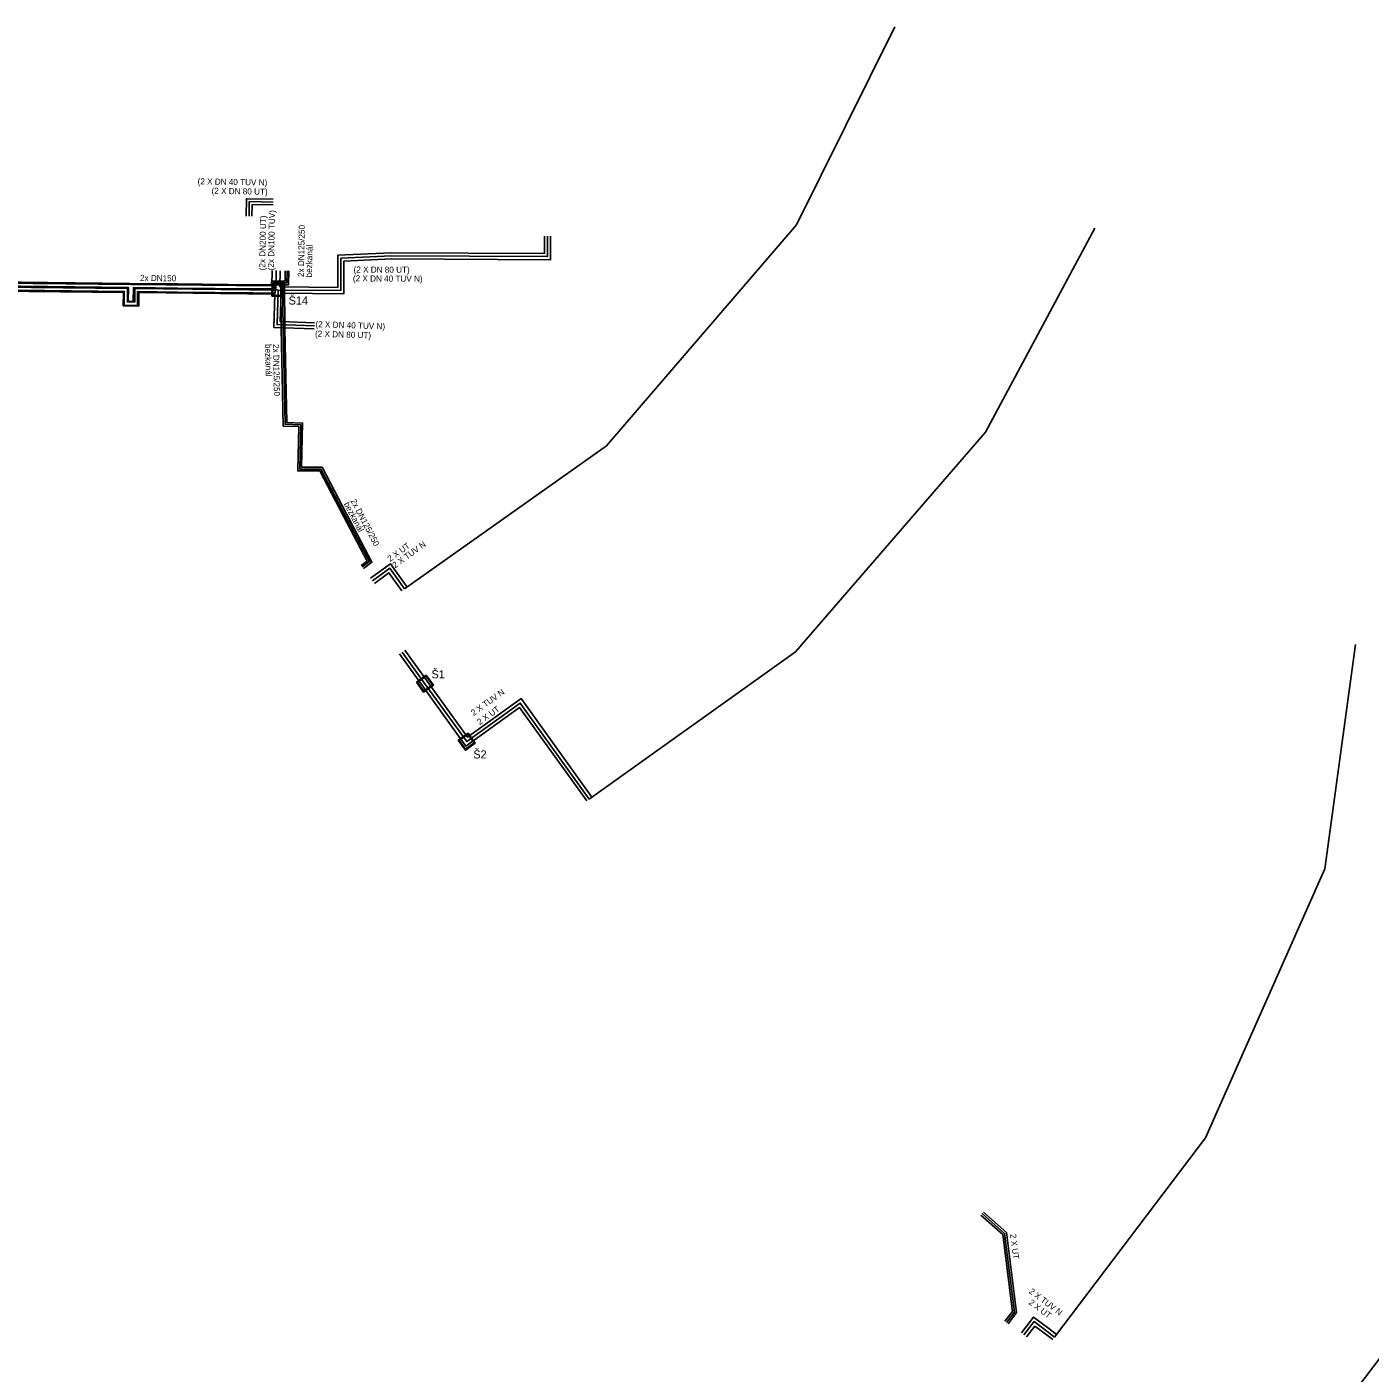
# Model space of a CAD drawing. Extents: x -606118 to -604472, y -1157869 to -1156854.
# Drawn here: x -605139.3 to -604808.5, y -1157466.1 to -1157134.5 of the extents above; entities that cross this region are included whole.
import ezdxf

# ---------------------------------------------------------------- set-up
doc = ezdxf.new("R2010")
doc.units = 0
for name, color, linetype in [('Osa trasy teplovodu', 7, 'Continuous'), ('označení šachty', 7, 'Continuous'), ('Teplovod - trasa - okraj', 7, 'Continuous'), ('Teplovod - trasa popis', 7, 'Continuous'), ('Teplovod - trasa popis 2', 7, 'Continuous'), ('Šachta trasy teplovodu', 7, 'Continuous')]:
    doc.layers.add(name, color=color, linetype=linetype)

msp = doc.modelspace()

# ---------------------------------------------------------------- linework, layer by layer
at = {"layer": 'Osa trasy teplovodu'}
for p, q in [((-605077.9, -1157194.56), (-605078, -1157199.33)), ((-604829.05, -1157492.68), (-604799.91, -1157454.18)), ((-604888.12, -1157455.75), (-604886.18, -1157457.22))]:
    msp.add_line(p, q, dxfattribs=at)
for points in [[(-605046.31, -1157272.96), (-604996.53, -1157237.75), (-604949.8, -1157183.3), (-604925.57, -1157134.54)], [(-605084.59, -1157181.14), (-605084.54, -1157177.57), (-605078.66, -1157177.68)], [(-605077.45, -1157199.34), (-605062, -1157199.5), (-605061.98, -1157191.49), (-605049.54, -1157190.9), (-605011.1, -1157191.11), (-605011.09, -1157186.11)], [(-605000.79, -1157324.72), (-604950.04, -1157288.49), (-604903.17, -1157234.33), (-604876.29, -1157184.14)], [(-605076.34, -1157197.59), (-605075.3, -1157197.59), (-605075.24, -1157194.62)], [(-605169.85, -1157198.38), (-605114.56, -1157198.95), (-605114.57, -1157202.26), (-605112.73, -1157202.28), (-605112.71, -1157198.97), (-605077.45, -1157199.34)], [(-605169.6, -1157198.05), (-605167.51, -1157198.07), (-605114.32, -1157198.71), (-605114.34, -1157202.16), (-605113.1, -1157202.17), (-605113.05, -1157198.72), (-605102.26, -1157198.85), (-605083.64, -1157199.07), (-605082.78, -1157199.08), (-605078.61, -1157199.08)], [(-605078.61, -1157199.08), (-605078.61, -1157197.59), (-605076.34, -1157197.59)], [(-605077.45, -1157199.34), (-605077.7, -1157207.84), (-605068.51, -1157208.14)], [(-605076.34, -1157197.59), (-605076.2, -1157208.81), (-605075.96, -1157220.61), (-605075.73, -1157232.41), (-605071.86, -1157232.54), (-605072.13, -1157243.45), (-605066.88, -1157243.43), (-605060.9, -1157254.84), (-605054.92, -1157266.24), (-605056.7, -1157267.54)], [(-605054.2, -1157270.97), (-605049.96, -1157267.88), (-605046.31, -1157272.96)], [(-605046.91, -1157288.51), (-605041.28, -1157296.3), (-605030.98, -1157310.58), (-605017.79, -1157301.06), (-605000.79, -1157324.72)], [(-604886.18, -1157457.22), (-604849.05, -1157408.16), (-604819.65, -1157341.94), (-604812.06, -1157286.61)], [(-604898.01, -1157453.62), (-604896.07, -1157451.08), (-604898.51, -1157431.7), (-604904, -1157426.83)], [(-604893.74, -1157456.7), (-604891.2, -1157453.43), (-604888.12, -1157455.75)]]:
    msp.add_lwpolyline(points, dxfattribs=at)
at = {"layer": 'Teplovod - trasa - okraj'}
for p, q in [((-605078.9, -1157194.54), (-605078.98, -1157198.32)), ((-605076.9, -1157194.58), (-605076.98, -1157198.59)), ((-604886.66, -1157457.85), (-604888.61, -1157456.39)), ((-604887.64, -1157455.11), (-604885.7, -1157456.58))]:
    msp.add_line(p, q, dxfattribs=at)
for points in [[(-605046.31, -1157272.96), (-604996.53, -1157237.75), (-604949.8, -1157183.3), (-604925.57, -1157134.54)], [(-605085.29, -1157181.12), (-605085.23, -1157176.86), (-605078.65, -1157176.98)], [(-605083.89, -1157181.15), (-605083.85, -1157178.29), (-605078.67, -1157178.38)], [(-605076.98, -1157198.59), (-605062.75, -1157198.74), (-605062.73, -1157190.78), (-605049.55, -1157190.15), (-605011.85, -1157190.36), (-605011.84, -1157186.11)], [(-605076.72, -1157200.09), (-605061.25, -1157200.26), (-605061.23, -1157192.21), (-605049.52, -1157191.65), (-605010.35, -1157191.87), (-605010.34, -1157186.11)], [(-605000.79, -1157324.72), (-604950.04, -1157288.49), (-604903.17, -1157234.33), (-604876.29, -1157184.14)], [(-605076.34, -1157197.15), (-605075.74, -1157197.15), (-605075.69, -1157194.61)], [(-605074.79, -1157194.63), (-605074.85, -1157198.04), (-605075.89, -1157198.04)], [(-605170.04, -1157197.05), (-605167.5, -1157197.07), (-605114.03, -1157197.71), (-605114.03, -1157197.7), (-605102.25, -1157197.85), (-605083.63, -1157198.07), (-605082.78, -1157198.08), (-605079.06, -1157198.08)], [(-605078.23, -1157200.33), (-605111.72, -1157199.98), (-605111.74, -1157203.28), (-605115.57, -1157203.25), (-605115.56, -1157199.94), (-605169.86, -1157199.38)], [(-605169.84, -1157197.38), (-605113.71, -1157197.96), (-605113.71, -1157197.96), (-605078.98, -1157198.32)], [(-605078.17, -1157200.08), (-605082.79, -1157200.08), (-605083.65, -1157200.07), (-605102.27, -1157199.85), (-605112.06, -1157199.73), (-605112.11, -1157203.19), (-605115.35, -1157203.14), (-605115.32, -1157199.69), (-605167.52, -1157199.07), (-605169.15, -1157199.06)], [(-605079.06, -1157198.08), (-605079.06, -1157197.14), (-605076.34, -1157197.15)], [(-605076.79, -1157198.04), (-605078.16, -1157198.04), (-605078.17, -1157200.08)], [(-605056.96, -1157267.17), (-605055.5, -1157266.11), (-605061.3, -1157255.05), (-605067.15, -1157243.88), (-605072.59, -1157243.9), (-605072.32, -1157232.98), (-605076.17, -1157232.84), (-605076.41, -1157220.62), (-605076.65, -1157208.82), (-605076.79, -1157198.04)], [(-605075.89, -1157198.04), (-605075.75, -1157208.8), (-605075.51, -1157220.6), (-605075.28, -1157231.98), (-605071.4, -1157232.11), (-605071.67, -1157243), (-605066.61, -1157242.98), (-605060.5, -1157254.63), (-605054.34, -1157266.38), (-605056.43, -1157267.9)], [(-605078.23, -1157200.33), (-605078.47, -1157208.56), (-605068.54, -1157208.89)], [(-605076.72, -1157200.09), (-605076.93, -1157207.11), (-605068.49, -1157207.39)], [(-605054.68, -1157270.32), (-605049.78, -1157266.76), (-605045.66, -1157272.5)], [(-605053.73, -1157271.62), (-605050.14, -1157269), (-605046.96, -1157273.43)], [(-605047.56, -1157288.98), (-605031.17, -1157311.7), (-605017.97, -1157302.18), (-605001.44, -1157325.19)], [(-605046.26, -1157288.04), (-605030.8, -1157309.46), (-605017.61, -1157299.94), (-605000.14, -1157324.26)], [(-604886.18, -1157457.22), (-604849.05, -1157408.16), (-604819.65, -1157341.94), (-604812.06, -1157286.61)], [(-604898.41, -1157453.32), (-604896.59, -1157450.94), (-604898.98, -1157431.95), (-604904.33, -1157427.21)], [(-604897.61, -1157453.93), (-604895.55, -1157451.22), (-604898.04, -1157431.45), (-604903.67, -1157426.46)], [(-604894.37, -1157456.21), (-604891.35, -1157452.31), (-604891.35, -1157452.31), (-604887.64, -1157455.11)], [(-604888.61, -1157456.39), (-604891.05, -1157454.54), (-604893.11, -1157457.19)]]:
    msp.add_lwpolyline(points, dxfattribs=at)
at = {"layer": 'Šachta trasy teplovodu'}
for points in [[(-605078.97, -1157200.82), (-605078.94, -1157197.82), (-605075.93, -1157197.85), (-605075.96, -1157200.85), (-605078.97, -1157200.82)], [(-605076.15, -1157200.66), (-605076.12, -1157198.03), (-605078.75, -1157198.01), (-605078.78, -1157200.64), (-605076.15, -1157200.66)], [(-605043.38, -1157295.96), (-605040.94, -1157294.21), (-605039.18, -1157296.64), (-605041.62, -1157298.4), (-605043.38, -1157295.96)], [(-605041.58, -1157298.14), (-605039.44, -1157296.6), (-605040.98, -1157294.47), (-605043.12, -1157296.01), (-605041.58, -1157298.14)], [(-605033.08, -1157310.24), (-605030.64, -1157308.48), (-605028.88, -1157310.92), (-605031.32, -1157312.68), (-605033.08, -1157310.24)], [(-605031.28, -1157312.41), (-605029.15, -1157310.88), (-605030.68, -1157308.74), (-605032.82, -1157310.28), (-605031.28, -1157312.41)]]:
    msp.add_lwpolyline(points, dxfattribs=at)

# ---------------------------------------------------------------- texts
at = {"layer": 'označení šachty'}
for s, p in [('Š14', (-605074.85, -1157202.93)), ('Š1', (-605039.66, -1157294.98)), ('Š2', (-605029.36, -1157314.72))]:
    msp.add_text(s, height=2, dxfattribs=at).set_placement(p)
at = {"layer": 'Teplovod - trasa popis'}
for s, rotation, p in [('(2 X DN 80 UT)', 359.0153, (-605093.84, -1157175.65)), ('(2x DN200 UT)', 88.8701, (-605080.64, -1157194.5)), ('2x DN125/250', 88.8646, (-605071.1, -1157196.15)), ('2x DN150', 359.3064, (-605111.47, -1157197.11)), ('(2 X DN 80 UT)', 359.7029, (-605058.85, -1157195.04)), ('(2 X DN 80 UT)', 358.1559, (-605068.37, -1157210.82)), ('2x DN125/250', 271.141, (-605078.71, -1157212.65)), ('2x DN125/250', 297.6804, (-605059.66, -1157251.26)), ('2 X UT', 36.039, (-605049.84, -1157266.34)), ('2 X UT', 35.8099, (-605027.77, -1157306.55)), ('2 X UT ', 277.197, (-604897.16, -1157431.92)), ('2 X UT ', 322.9763, (-604892.7, -1157448.99))]:
    msp.add_text(s, height=1.5, rotation=rotation, dxfattribs=at).set_placement(p)
at = {"layer": 'Teplovod - trasa popis 2'}
for s, rotation, p in [('(2 X DN 40 TUV N)', 359.0153, (-605097.28, -1157173.31)), ('(2x DN100 TUV)', 88.8701, (-605078.48, -1157194.5)), ('bezkanál', 88.8646, (-605069.11, -1157196.24)), ('(2 X DN 40 TUV N)', 359.7029, (-605059.02, -1157197.22)), ('(2 X DN 40 TUV N)', 358.1559, (-605068.26, -1157208.49)), ('bezkanál', 271.141, (-605080.64, -1157212.65)), ('bezkanál', 297.6804, (-605061.3, -1157252.03)), ('2 X TUV N', 36.039, (-605048.63, -1157267.94)), ('2 X TUV N', 35.8099, (-605029.29, -1157304.3)), ('2 X TUV N', 322.9763, (-604892.64, -1157446.25))]:
    msp.add_text(s, height=1.5, rotation=rotation, dxfattribs=at).set_placement(p)

doc.saveas('drawing.dxf')
